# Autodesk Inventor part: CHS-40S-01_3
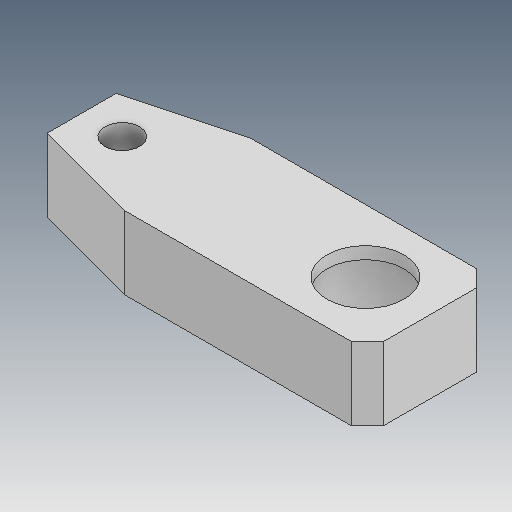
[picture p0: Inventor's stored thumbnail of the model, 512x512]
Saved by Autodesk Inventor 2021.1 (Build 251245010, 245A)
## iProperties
Created: 2019-05
Part Number: CHS-40S-01_3
Material: Ogólny
Document SubType Name: Modeling
Designer: user
Density: 1 g/cm^3
Appearance: Domyślna
Author: user
Revision Number: ÈÎºÎ
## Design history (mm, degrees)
feature "ÊäÈë1"
node "Bryła1"
